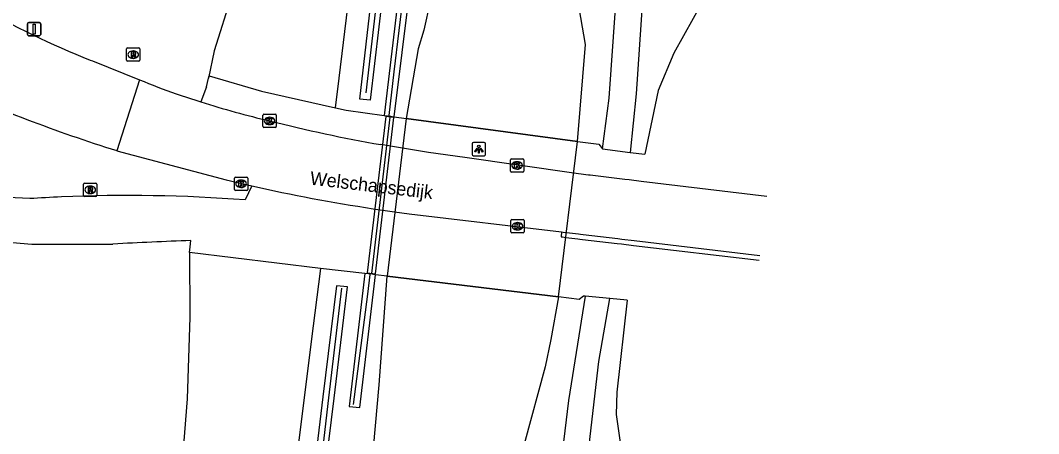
# Model space of a CAD drawing. Extents: x 156061 to 157804, y 383451 to 385640.
# Drawn here: x 157695.1 to 157771.7, y 383638.4 to 383669.5 of the extents above; entities that cross this region are included whole.
import ezdxf

# ---------------------------------------------------------------- set-up
doc = ezdxf.new("R2010")
doc.units = 0
for name, color, linetype in [('IMGEO_Afsluitpaal', 7, 'Continuous'), ('IMGEO_Berm_groen', 7, 'Continuous'), ('IMGEO_Fietspad_gesloten', 7, 'Continuous'), ('IMGEO_Geluidsscherm', 7, 'Continuous'), ('IMGEO_Grasland_overig', 7, 'Continuous'), ('IMGEO_Groenvoorziening', 7, 'Continuous'), ('IMGEO_Kolk', 7, 'Continuous'), ('IMGEO_Lichtpunt', 7, 'Continuous'), ('IMGEO_Muur', 7, 'Continuous'), ('IMGEO_Openbare_ruimte_label', 7, 'Continuous'), ('IMGEO_Rijbaan_autosnelweg', 7, 'Continuous'), ('IMGEO_Rijbaan_autoweg', 7, 'Continuous'), ('IMGEO_Rijbaan_lokaal_gesloten', 7, 'Continuous'), ('IMGEO_Rijbaan_lokaal_open', 7, 'Continuous'), ('IMGEO_Rioolput', 7, 'Continuous'), ('IMGEO_Voetpad_gesloten', 7, 'Continuous')]:
    doc.layers.add(name, color=color, linetype=linetype)

msp = doc.modelspace()

# ---------------------------------------------------------------- linework, layer by layer
at = {"layer": 'IMGEO_Afsluitpaal'}
for p, q in [((157695.666, 383668.453), (157695.666, 383669.253)), ((157695.666, 383669.253), (157695.666, 383668.453)), ((157695.766, 383669.353), (157696.556, 383669.353)), ((157696.556, 383669.353), (157695.766, 383669.353)), ((157696.656, 383669.253), (157696.656, 383668.453)), ((157696.656, 383668.453), (157696.656, 383669.253)), ((157696.556, 383668.353), (157695.766, 383668.353)), ((157695.766, 383668.353), (157696.556, 383668.353))]:
    msp.add_line(p, q, dxfattribs=at)
msp.add_lwpolyline([(157696.086, 383669.228), (157696.236, 383669.228), (157696.236, 383668.478), (157696.086, 383668.478), (157696.086, 383669.228)], dxfattribs=at)
for centre, start, end in [((157695.766, 383669.253), 90, 180), ((157695.766, 383669.253), 90, 180), ((157696.556, 383669.253), 0, 90), ((157696.556, 383669.253), 360, 90), ((157695.766, 383668.453), 180, 270), ((157695.766, 383668.453), 180, 270), ((157696.556, 383668.453), 270, 0), ((157696.556, 383668.453), 270, 0)]:
    msp.add_arc(centre, 0.1, start, end, dxfattribs=at)
at = {"layer": 'IMGEO_Berm_groen'}
for points in [[(157738.92, 383659.835), (157739.44, 383663.652), (157739.912, 383670.397), (157741.598, 383680.641), (157742.806, 383693.693), (157743.869, 383704.059), (157744.981, 383712.874), (157746.845, 383725.741), (157747.943, 383737.666), (157750.001, 383751.204), (157750.852, 383762.776), (157752.031, 383773.44), (157754.009, 383786.672), (157755.035, 383796.215), (157756.236, 383808.352), (157757.884, 383821.776), (157759.11, 383833.027), (157760.417, 383843.772), (157761.507, 383853.149), (157762.754, 383863.571), (157764.121, 383875.018)], [(157718.842, 383662.923), (157719.108, 383665.149), (157720.092, 383673.241), (157721.228, 383686.096), (157723.015, 383698.147), (157724.798, 383710.705), (157725.901, 383723.023), (157726.484, 383733.729)], [(157741.95, 383671.056), (157741.473, 383663.974), (157741.005, 383659.578)], [(157718.842, 383662.923), (157719.638, 383662.743), (157722.502, 383662.358)], [(157723.243, 383662.258), (157724.148, 383662.136)], [(157737.057, 383660.4), (157738.654, 383660.185), (157738.92, 383659.835)], [(157741.005, 383659.578), (157742.101, 383659.442)], [(157717.713, 383650.843), (157716.995, 383645.35), (157715.214, 383631.092), (157712.289, 383614.469), (157709.211, 383596.79), (157706.614, 383581.755), (157704.19, 383566.51)], [(157721.038, 383650.469), (157717.713, 383650.843)], [(157722.732, 383650.277), (157721.859, 383650.376)], [(157733.004, 383587.922), (157734.583, 383599.341), (157735.819, 383608.957), (157736.639, 383618.461), (157737.387, 383627.877), (157737.937, 383637.566), (157738.654, 383643.844), (157739.492, 383648.575)], [(157737.626, 383648.75), (157736.367, 383640.916), (157735.353, 383632.405), (157734.475, 383623.18)], [(157737.626, 383648.75), (157737.487, 383648.763), (157737.165, 383648.499), (157735.627, 383648.709)], [(157740.782, 383648.454), (157739.492, 383648.575)]]:
    msp.add_lwpolyline(points, dxfattribs=at)
at = {"layer": 'IMGEO_Fietspad_gesloten'}
for points in [[(157695.831, 383656.1), (157690.319, 383656.355), (157689.639, 383656.466), (157687.233, 383657.083), (157684.891, 383657.914), (157682.633, 383658.95), (157679.835, 383661.037), (157676.91, 383663.632), (157674.228, 383666.477), (157671.072, 383670.09)], [(157677.351, 383659.207), (157680.92, 383656.58), (157683.3, 383654.951), (157687.249, 383653.73), (157692.2, 383653.007), (157695.992, 383652.677), (157702.093, 383652.679)], [(157712.545, 383657.066), (157712.033, 383655.999)], [(157735.848, 383653.589), (157735.814, 383653.226), (157735.925, 383653.213), (157736.174, 383653.183), (157737.07, 383653.077), (157737.228, 383653.059), (157737.428, 383653.035), (157740.027, 383652.728), (157740.346, 383652.69), (157741.268, 383652.581), (157750.722, 383651.464), (157750.722, 383651.464)]]:
    msp.add_lwpolyline(points, dxfattribs=at)
for centre, radius, start, end in [((157702.758, 383546.935), 109.385, 92.38228, 93.63066), ((157703.219, 383539.719), 116.614, 85.66523, 92.46128), ((157720.456, 383313.145), 340.03, 92.10848, 93.09575)]:
    msp.add_arc(centre, radius, start, end, dxfattribs=at)
at = {"layer": 'IMGEO_Geluidsscherm'}
for points in [[(157726.919, 383713.541), (157725.935, 383705.238), (157725.006, 383696.937), (157723.968, 383688.557), (157723.006, 383680.18), (157722.022, 383671.858), (157721.109, 383664.045)], [(157722.865, 383662.353), (157723.252, 383665.627), (157724.016, 383671.87)], [(157721.564, 383650.473), (157722.952, 383662.235)], [(157720.192, 383640.603), (157721.278, 383648.91), (157721.453, 383650.39)], [(157719.296, 383649.357), (157718.318, 383641.119), (157717.359, 383632.855), (157716.065, 383624.566), (157714.698, 383616.228), (157713.336, 383607.983), (157712.023, 383599.694), (157710.597, 383591.409), (157708.989, 383581.514), (157707.832, 383576.94), (157706.443, 383568.03), (157705.668, 383563.817)]]:
    msp.add_lwpolyline(points, dxfattribs=at)
at = {"layer": 'IMGEO_Grasland_overig'}
for points in [[(157711.048, 383671.456), (157709.713, 383667.202), (157709.269, 383665.15)], [(157709.269, 383665.15), (157709.322, 383665.321), (157713.264, 383664.187), (157718.842, 383662.923)], [(157738.92, 383659.835), (157741.005, 383659.578)], [(157707.846, 383652.051), (157707.868, 383647.188), (157707.686, 383641.031), (157706.863, 383630.921), (157706.51, 383628.347), (157706.411, 383627.62), (157706.014, 383624.729), (157705.903, 383623.92)], [(157717.713, 383650.843), (157707.846, 383652.051)], [(157739.492, 383648.575), (157737.626, 383648.75)]]:
    msp.add_lwpolyline(points, dxfattribs=at)
at = {"layer": 'IMGEO_Groenvoorziening'}
for points in [[(157709.13, 383664.506), (157709.131, 383664.512), (157709.269, 383665.15)], [(157707.846, 383652.051), (157707.894, 383652.483), (157707.946, 383652.945)]]:
    msp.add_lwpolyline(points, dxfattribs=at)
at = {"layer": 'IMGEO_Kolk'}
for p, q in [((157713.382, 383661.514), (157713.382, 383662.366)), ((157713.457, 383662.44), (157714.309, 383662.44)), ((157713.87, 383662.22), (157713.895, 383662.22)), ((157714.383, 383662.366), (157714.383, 383661.514)), ((157714.309, 383661.44), (157713.457, 383661.44)), ((157713.893, 383661.66), (157713.868, 383661.66)), ((157731.996, 383658.17), (157731.996, 383659.022)), ((157732.071, 383659.096), (157732.923, 383659.096)), ((157732.997, 383659.022), (157732.997, 383658.17)), ((157732.507, 383658.316), (157732.482, 383658.316)), ((157732.484, 383658.876), (157732.509, 383658.876)), ((157711.237, 383656.791), (157711.237, 383657.643)), ((157711.312, 383657.717), (157712.164, 383657.717)), ((157711.725, 383657.497), (157711.75, 383657.497)), ((157712.238, 383657.643), (157712.238, 383656.791)), ((157732.923, 383658.096), (157732.071, 383658.096)), ((157712.164, 383656.717), (157711.312, 383656.717)), ((157711.748, 383656.937), (157711.723, 383656.937)), ((157732.038, 383653.592), (157732.038, 383654.444)), ((157732.113, 383654.518), (157732.965, 383654.518)), ((157733.039, 383654.444), (157733.039, 383653.592)), ((157732.549, 383653.738), (157732.524, 383653.738)), ((157732.526, 383654.298), (157732.551, 383654.298)), ((157732.965, 383653.518), (157732.113, 383653.518))]:
    msp.add_line(p, q, dxfattribs=at)
for points in [[(157713.382, 383661.514), (157713.382, 383662.366)], [(157713.457, 383662.44), (157714.309, 383662.44)], [(157713.703, 383662.14), (157713.826, 383662.14), (157713.826, 383661.989), (157713.956, 383662.14), (157714.12, 383662.14), (157713.974, 383661.989), (157714.127, 383661.74), (157713.975, 383661.74), (157713.89, 383661.904), (157713.826, 383661.837), (157713.826, 383661.74), (157713.703, 383661.74), (157713.703, 383662.14)], [(157714.383, 383662.366), (157714.383, 383661.514)], [(157714.309, 383661.44), (157713.457, 383661.44)], [(157731.996, 383658.17), (157731.996, 383659.022)], [(157732.071, 383659.096), (157732.923, 383659.096)], [(157732.997, 383659.022), (157732.997, 383658.17)], [(157732.317, 383658.796), (157732.44, 383658.796), (157732.44, 383658.645), (157732.57, 383658.796), (157732.734, 383658.796), (157732.588, 383658.645), (157732.741, 383658.396), (157732.589, 383658.396), (157732.504, 383658.56), (157732.44, 383658.493), (157732.44, 383658.396), (157732.317, 383658.396), (157732.317, 383658.796)], [(157711.237, 383656.791), (157711.237, 383657.643)], [(157711.312, 383657.717), (157712.164, 383657.717)], [(157712.238, 383657.643), (157712.238, 383656.791)], [(157732.923, 383658.096), (157732.071, 383658.096)], [(157712.164, 383656.717), (157711.312, 383656.717)], [(157711.558, 383657.417), (157711.681, 383657.417), (157711.681, 383657.266), (157711.811, 383657.417), (157711.975, 383657.417), (157711.829, 383657.266), (157711.982, 383657.017), (157711.83, 383657.017), (157711.745, 383657.181), (157711.681, 383657.114), (157711.681, 383657.017), (157711.558, 383657.017), (157711.558, 383657.417)], [(157732.038, 383653.592), (157732.038, 383654.444)], [(157732.113, 383654.518), (157732.965, 383654.518)], [(157733.039, 383654.444), (157733.039, 383653.592)], [(157732.359, 383654.218), (157732.482, 383654.218), (157732.482, 383654.067), (157732.612, 383654.218), (157732.776, 383654.218), (157732.63, 383654.067), (157732.783, 383653.818), (157732.631, 383653.818), (157732.546, 383653.982), (157732.482, 383653.915), (157732.482, 383653.818), (157732.359, 383653.818), (157732.359, 383654.218)], [(157732.965, 383653.518), (157732.113, 383653.518)]]:
    msp.add_lwpolyline(points, dxfattribs=at)
for centre, start, end in [((157713.459, 383662.364), 91.55205, 178.44795), ((157713.459, 383662.364), 91.55205, 178.44795), ((157714.307, 383662.364), 1.55205, 88.44795), ((157714.307, 383662.364), 1.55205, 88.44795), ((157713.459, 383661.516), 181.55205, 268.44795), ((157713.459, 383661.516), 181.55205, 268.44795), ((157714.307, 383661.516), 271.55205, 358.44795), ((157714.307, 383661.516), 271.55205, 358.44795), ((157732.073, 383659.02), 91.55205, 178.44795), ((157732.073, 383659.02), 91.55205, 178.44795), ((157732.921, 383659.02), 1.55205, 88.44795), ((157732.921, 383659.02), 1.55205, 88.44795), ((157711.314, 383657.641), 91.55205, 178.44795), ((157711.314, 383657.641), 91.55205, 178.44795), ((157712.162, 383657.641), 1.55205, 88.44795), ((157712.162, 383657.641), 1.55205, 88.44795), ((157732.073, 383658.172), 181.55205, 268.44795), ((157732.073, 383658.172), 181.55205, 268.44795), ((157732.921, 383658.172), 271.55205, 358.44795), ((157732.921, 383658.172), 271.55205, 358.44795), ((157711.314, 383656.793), 181.55205, 268.44795), ((157711.314, 383656.793), 181.55205, 268.44795), ((157712.162, 383656.793), 271.55205, 358.44795), ((157712.162, 383656.793), 271.55205, 358.44795), ((157732.115, 383654.442), 91.55205, 178.44795), ((157732.115, 383654.442), 91.55205, 178.44795), ((157732.963, 383654.442), 1.55205, 88.44795), ((157732.963, 383654.442), 1.55205, 88.44795), ((157732.115, 383653.594), 181.55205, 268.44795), ((157732.115, 383653.594), 181.55205, 268.44795), ((157732.963, 383653.594), 271.55205, 358.44795), ((157732.963, 383653.594), 271.55205, 358.44795)]:
    msp.add_arc(centre, 0.0765, start, end, dxfattribs=at)
for centre, major_axis, ratio, start_param, end_param in [((157713.869, 383661.94), (-0.387, 0.002), 0.722429, 4.712389, 7.853982), ((157713.894, 383661.94), (-0.39, 0.002), 0.717154, 1.570796, 4.712389), ((157732.483, 383658.596), (-0.387, 0.002), 0.722429, 4.712389, 7.853982), ((157732.508, 383658.596), (-0.39, 0.002), 0.717154, 1.570796, 4.712389), ((157711.724, 383657.217), (-0.387, 0.002), 0.722429, 4.712389, 7.853982), ((157711.749, 383657.217), (-0.39, 0.002), 0.717154, 1.570796, 4.712389), ((157732.525, 383654.018), (-0.387, 0.002), 0.722429, 4.712389, 7.853982), ((157732.55, 383654.018), (-0.39, 0.002), 0.717154, 1.570796, 4.712389)]:
    msp.add_ellipse(centre, major_axis=major_axis, ratio=ratio, start_param=start_param, end_param=end_param, dxfattribs=at)
at = {"layer": 'IMGEO_Lichtpunt'}
for p, q in [((157729.126, 383660.229), (157729.126, 383659.422)), ((157729.126, 383660.229), (157729.126, 383659.422)), ((157730.028, 383660.324), (157729.22, 383660.324)), ((157730.028, 383660.324), (157729.22, 383660.324)), ((157730.122, 383659.422), (157730.122, 383660.229)), ((157730.122, 383659.422), (157730.122, 383660.229)), ((157729.22, 383659.328), (157730.028, 383659.328)), ((157729.22, 383659.328), (157730.028, 383659.328))]:
    msp.add_line(p, q, dxfattribs=at)
for points in [[(157729.5, 383659.893), (157729.539, 383659.865), (157729.351, 383659.603), (157729.313, 383659.63), (157729.5, 383659.893)], [(157729.602, 383659.845), (157729.649, 383659.845), (157729.649, 383659.523), (157729.602, 383659.523), (157729.602, 383659.845)], [(157729.712, 383659.865), (157729.75, 383659.892), (157729.937, 383659.63), (157729.898, 383659.602), (157729.712, 383659.865)]]:
    msp.add_lwpolyline(points, dxfattribs=at)
msp.add_circle((157729.625, 383660.027), 0.0994, dxfattribs=at)
for centre, start, end in [((157729.22, 383660.229), 90, 180), ((157729.22, 383660.229), 90, 180), ((157730.028, 383660.229), 0, 90), ((157730.028, 383660.229), 0, 90), ((157729.22, 383659.422), 180, 270), ((157729.22, 383659.422), 180, 270), ((157730.028, 383659.422), 270, 0), ((157730.028, 383659.422), 270, 360)]:
    msp.add_arc(centre, 0.0946, start, end, dxfattribs=at)
at = {"layer": 'IMGEO_Muur'}
for points in [[(157723.243, 383662.258), (157724.445, 383671.962), (157723.664, 383672.04), (157722.502, 383662.358)], [(157722.419, 383671.81), (157721.435, 383663.498), (157720.663, 383663.576), (157721.629, 383671.888)], [(157723.231, 383662.206), (157722.615, 383662.278), (157721.225, 383650.504), (157721.841, 383650.431), (157723.231, 383662.206)], [(157722.502, 383662.358), (157723.009, 383662.29), (157723.108, 383662.276), (157723.243, 383662.258)], [(157721.038, 383650.469), (157719.857, 383640.466), (157720.675, 383640.38), (157721.859, 383650.376)], [(157721.859, 383650.376), (157721.705, 383650.393), (157721.606, 383650.405), (157721.038, 383650.469)], [(157706.088, 383563.751), (157707.514, 383572.027), (157708.267, 383576.864), (157709.39, 383581.371), (157711.006, 383591.294), (157712.402, 383599.624), (157713.754, 383607.869), (157715.133, 383616.152), (157716.494, 383624.434), (157717.712, 383632.747), (157718.732, 383641.098), (157719.733, 383649.458), (157718.905, 383649.544), (157717.894, 383641.202), (157716.883, 383632.851), (157715.681, 383624.595), (157714.312, 383616.303), (157712.943, 383608.011), (157711.583, 383599.729), (157710.195, 383591.427), (157708.594, 383581.589), (157707.462, 383577.063), (157706.685, 383572.141), (157705.296, 383563.876)]]:
    msp.add_lwpolyline(points, dxfattribs=at)
at = {"layer": 'IMGEO_Rijbaan_autosnelweg'}
for points in [[(157771.745, 383878.769), (157769.81, 383863.086), (157767.764, 383845.831), (157765.716, 383827.84), (157763.603, 383810.789), (157761.619, 383793.424), (157760.381, 383783.191), (157758.432, 383766.262), (157757.27, 383757.58), (157755.872, 383746), (157751.82, 383712.586), (157750.61, 383699.987), (157749.445, 383690.253), (157748.398, 383681.217), (157747.549, 383674.09), (157747.198, 383672.277), (157744.3, 383667.036), (157743.111, 383664.24), (157742.101, 383659.442)], [(157740.782, 383648.454), (157739.996, 383641.532), (157739.966, 383639.854), (157740.281, 383637.583), (157741.807, 383629.689), (157742.021, 383628.219), (157741.178, 383620.522), (157739.826, 383609.505), (157738.489, 383598.555), (157737.251, 383587.909), (157735.931, 383577.194), (157734.539, 383565.38), (157733.187, 383553.895)]]:
    msp.add_lwpolyline(points, dxfattribs=at)
at = {"layer": 'IMGEO_Rijbaan_autoweg'}
for points in [[(157737.057, 383660.4), (157737.637, 383667.683), (157737.079, 383671.011), (157737.249, 383673.97), (157738.386, 383683.711), (157740.58, 383700.758), (157741.843, 383712.697), (157743.7, 383727.433), (157745.117, 383738.448), (157746.4, 383750.061), (157747.962, 383762.149), (157749.345, 383773.276), (157750.798, 383785.473), (157752.262, 383797.641), (157753.664, 383808.76), (157755.096, 383821.767), (157756.285, 383832.233), (157757.648, 383843.746), (157758.934, 383854.34), (157760.37, 383866.894), (157761.647, 383877.864)], [(157741.487, 383800.888), (157740.503, 383792.575), (157738.654, 383778.454), (157737.65, 383768.714), (157735.932, 383754.482), (157734.396, 383742.421), (157732.786, 383727.807), (157730.885, 383712.196), (157729.521, 383700.57), (157728.307, 383690.881), (157726.998, 383680.128), (157725.95, 383670.924), (157725.492, 383668.778), (157725.067, 383667.364), (157724.148, 383662.136)], [(157737.057, 383660.4), (157724.148, 383662.136), (157722.732, 383650.277), (157735.627, 383648.709), (157737.057, 383660.4)], [(157724.148, 383662.136), (157737.057, 383660.4)], [(157709.84, 383562.562), (157712.065, 383575.48), (157714.141, 383587.315), (157715.92, 383598.218), (157718.034, 383610.448), (157719.143, 383617.417), (157720.321, 383624.736), (157721.018, 383629.758), (157722.127, 383642.084), (157722.732, 383650.277)], [(157735.627, 383648.709), (157722.732, 383650.277)], [(157735.627, 383648.709), (157735.041, 383645.491), (157734.625, 383643.441), (157733.026, 383637.621), (157731.961, 383628.162), (157730.379, 383615.956), (157728.998, 383603.459), (157727.342, 383588.449), (157725.775, 383576.122), (157724.217, 383564.235), (157722.861, 383552.647)]]:
    msp.add_lwpolyline(points, dxfattribs=at)
at = {"layer": 'IMGEO_Rijbaan_lokaal_gesloten'}
for points in [[(157751.291, 383656.265), (157751.291, 383656.265), (157741.836, 383657.396), (157740.922, 383657.505), (157740.598, 383657.544), (157737.992, 383657.855), (157737.884, 383657.868), (157737.675, 383657.893), (157736.764, 383658.002), (157728.569, 383659.183), (157725.833, 383659.578), (157723.869, 383659.882), (157722.252, 383660.156)], [(157702.389, 383659.704), (157710.603, 383657.507), (157712.545, 383657.066)], [(157721.661, 383655.34), (157723.281, 383655.108), (157723.828, 383655.035), (157724.374, 383654.964), (157735.848, 383653.589)], [(157735.848, 383653.589), (157735.975, 383653.574), (157736.218, 383653.545), (157737.116, 383653.438), (157737.277, 383653.419), (157737.47, 383653.396), (157740.07, 383653.086), (157740.388, 383653.048), (157741.31, 383652.938), (157750.763, 383651.812), (157750.764, 383651.812)]]:
    msp.add_lwpolyline(points, dxfattribs=at)
for centre, radius, start, end in [((157721.196, 383705.446), 43.876, 247.05673, 250.90179), ((157721.965, 383707.851), 46.4, 250.97565, 253.40636), ((157729.064, 383726.3), 66.126, 252.07653, 256.7278), ((157743.63, 383780.964), 122.685, 255.96796, 259.96505), ((157739.724, 383775.677), 121.685, 257.09387, 261.46349)]:
    msp.add_arc(centre, radius, start, end, dxfattribs=at)
at = {"layer": 'IMGEO_Rijbaan_lokaal_open'}
for points in [[(157700.386, 383666.519), (157700.544, 383666.456), (157704.092, 383665.041)], [(157704.092, 383665.041), (157702.389, 383659.704)]]:
    msp.add_lwpolyline(points, dxfattribs=at)
for centre, radius, start, end in [((157723.738, 383725.44), 63.38, 239.81674, 248.37989), ((157736.579, 383769.162), 114.673, 245.47521, 252.6532)]:
    msp.add_arc(centre, radius, start, end, dxfattribs=at)
at = {"layer": 'IMGEO_Rioolput'}
for p, q in [((157703.19, 383667.427), (157704.042, 383667.427)), ((157703.115, 383666.501), (157703.115, 383667.353)), ((157703.626, 383666.647), (157703.601, 383666.647)), ((157703.603, 383667.207), (157703.628, 383667.207)), ((157704.116, 383667.353), (157704.116, 383666.501)), ((157704.042, 383666.427), (157703.19, 383666.427)), ((157699.878, 383656.336), (157699.878, 383657.188)), ((157699.953, 383657.262), (157700.805, 383657.262)), ((157700.366, 383657.042), (157700.391, 383657.042)), ((157700.879, 383657.188), (157700.879, 383656.336)), ((157700.805, 383656.262), (157699.953, 383656.262)), ((157700.389, 383656.482), (157700.364, 383656.482))]:
    msp.add_line(p, q, dxfattribs=at)
for points in [[(157703.19, 383667.427), (157704.042, 383667.427)], [(157703.115, 383666.501), (157703.115, 383667.353)], [(157703.704, 383667.125), (157703.452, 383667.127), (157703.452, 383666.727)], [(157703.452, 383666.727), (157703.576, 383666.727), (157703.576, 383666.889), (157703.587, 383666.889)], [(157703.63, 383667.046), (157703.576, 383667.046), (157703.576, 383666.965)], [(157703.576, 383666.965), (157703.628, 383666.965)], [(157703.634, 383666.86), (157703.705, 383666.727), (157703.845, 383666.727), (157703.78, 383666.853)], [(157704.116, 383667.353), (157704.116, 383666.501)], [(157704.042, 383666.427), (157703.19, 383666.427)], [(157699.878, 383656.336), (157699.878, 383657.188)], [(157699.953, 383657.262), (157700.805, 383657.262)], [(157700.467, 383656.96), (157700.215, 383656.962), (157700.215, 383656.562)], [(157700.215, 383656.562), (157700.339, 383656.562), (157700.339, 383656.724), (157700.35, 383656.724)], [(157700.393, 383656.881), (157700.339, 383656.881), (157700.339, 383656.8)], [(157700.339, 383656.8), (157700.391, 383656.8)], [(157700.397, 383656.695), (157700.468, 383656.562), (157700.608, 383656.562), (157700.543, 383656.688)], [(157700.879, 383657.188), (157700.879, 383656.336)], [(157700.805, 383656.262), (157699.953, 383656.262)]]:
    msp.add_lwpolyline(points, dxfattribs=at)
for centre, radius, start, end in [((157703.192, 383667.351), 0.0765, 91.55205, 178.44795), ((157703.192, 383667.351), 0.0765, 91.55205, 178.44795), ((157704.04, 383667.351), 0.0765, 1.55205, 88.44795), ((157704.04, 383667.351), 0.0765, 1.55205, 88.44795), ((157703.586, 383666.836), 0.0533, 26.02933, 88.69889), ((157703.612, 383667.154), 0.19, 274.7715, 282.96867), ((157703.636, 383666.95), 0.0964, 77.00612, 93.18647), ((157703.65, 383667.007), 0.0378, 276.66336, 79.67722), ((157703.703, 383667.015), 0.109, 350.36119, 89.41601), ((157703.701, 383667.015), 0.112, 277.58423, 350.98172), ((157703.685, 383666.8), 0.108, 29.51342, 73.79051), ((157703.192, 383666.503), 0.0765, 181.55205, 268.44795), ((157703.192, 383666.503), 0.0765, 181.55205, 268.44795), ((157704.04, 383666.503), 0.0765, 271.55205, 358.44795), ((157704.04, 383666.503), 0.0765, 271.55205, 358.44795), ((157699.955, 383657.186), 0.0765, 91.55205, 178.44795), ((157699.955, 383657.186), 0.0765, 91.55205, 178.44795), ((157700.349, 383656.671), 0.0533, 26.02933, 88.69889), ((157700.375, 383656.989), 0.19, 274.7715, 282.96867), ((157700.399, 383656.785), 0.0964, 77.00612, 93.18647), ((157700.413, 383656.842), 0.0378, 276.66336, 79.67722), ((157700.466, 383656.85), 0.109, 350.36119, 89.41601), ((157700.464, 383656.85), 0.112, 277.58423, 350.98172), ((157700.448, 383656.635), 0.108, 29.51342, 73.79051), ((157700.803, 383657.186), 0.0765, 1.55205, 88.44795), ((157700.803, 383657.186), 0.0765, 1.55205, 88.44795), ((157699.955, 383656.338), 0.0765, 181.55205, 268.44795), ((157699.955, 383656.338), 0.0765, 181.55205, 268.44795), ((157700.803, 383656.338), 0.0765, 271.55205, 358.44795), ((157700.803, 383656.338), 0.0765, 271.55205, 358.44795)]:
    msp.add_arc(centre, radius, start, end, dxfattribs=at)
for centre, major_axis, ratio, start_param, end_param in [((157703.602, 383666.927), (-0.387, 0.002), 0.722429, 4.712389, 7.853982), ((157703.627, 383666.927), (-0.39, 0.002), 0.717154, 1.570796, 4.712389), ((157700.365, 383656.762), (-0.387, 0.002), 0.722429, 4.712389, 7.853982), ((157700.39, 383656.762), (-0.39, 0.002), 0.717154, 1.570796, 4.712389)]:
    msp.add_ellipse(centre, major_axis=major_axis, ratio=ratio, start_param=start_param, end_param=end_param, dxfattribs=at)
at = {"layer": 'IMGEO_Voetpad_gesloten'}
msp.add_lwpolyline([(157709.13, 383664.506), (157708.714, 383663.383)], dxfattribs=at)

# ---------------------------------------------------------------- texts
at = {"layer": 'IMGEO_Openbare_ruimte_label'}
msp.add_text('Welschapsedijk', height=1, rotation=353.22322, dxfattribs=at).set_placement((157716.88, 383657.155))

doc.saveas('drawing.dxf')
